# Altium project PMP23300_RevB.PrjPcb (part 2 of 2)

## Sheet PMP23300_PD_Power_RevB.SchDoc
size 431 x 279 mm; Date: Not shown in title block; ApprovedBy: Not shown in title block; CheckedBy: Not shown in title block; Author: Not shown in title block; CompanyName: Not shown in title block; Engineer: Not shown in title block; Organization: Not shown in title block; Address1: Not shown in title block; Address2: Not shown in title block; Address3: Not shown in title block; Address4: Not shown in title block; DocumentNumber: 2; Revision: Use project parameter SCH_Rev; SheetNumber: 2; SheetTotal: 4; PageSetup: Record=PageOptions¦CenterHorizontal=True¦CenterVertical=True¦PrintScale=1.00¦XCorrection=1.00¦YCorrection=1.00¦PrintKind=0¦BorderSize=5000000¦LeftOffset=0¦BottomOffset=0¦Orientation=2¦PaperLength=1000¦PaperWidth=1000¦Scale=100¦PaperSource=15¦PrintQuality=600¦MediaType=1¦DitherType=10¦PaperKind=Letter¦PrintScaleMode=1
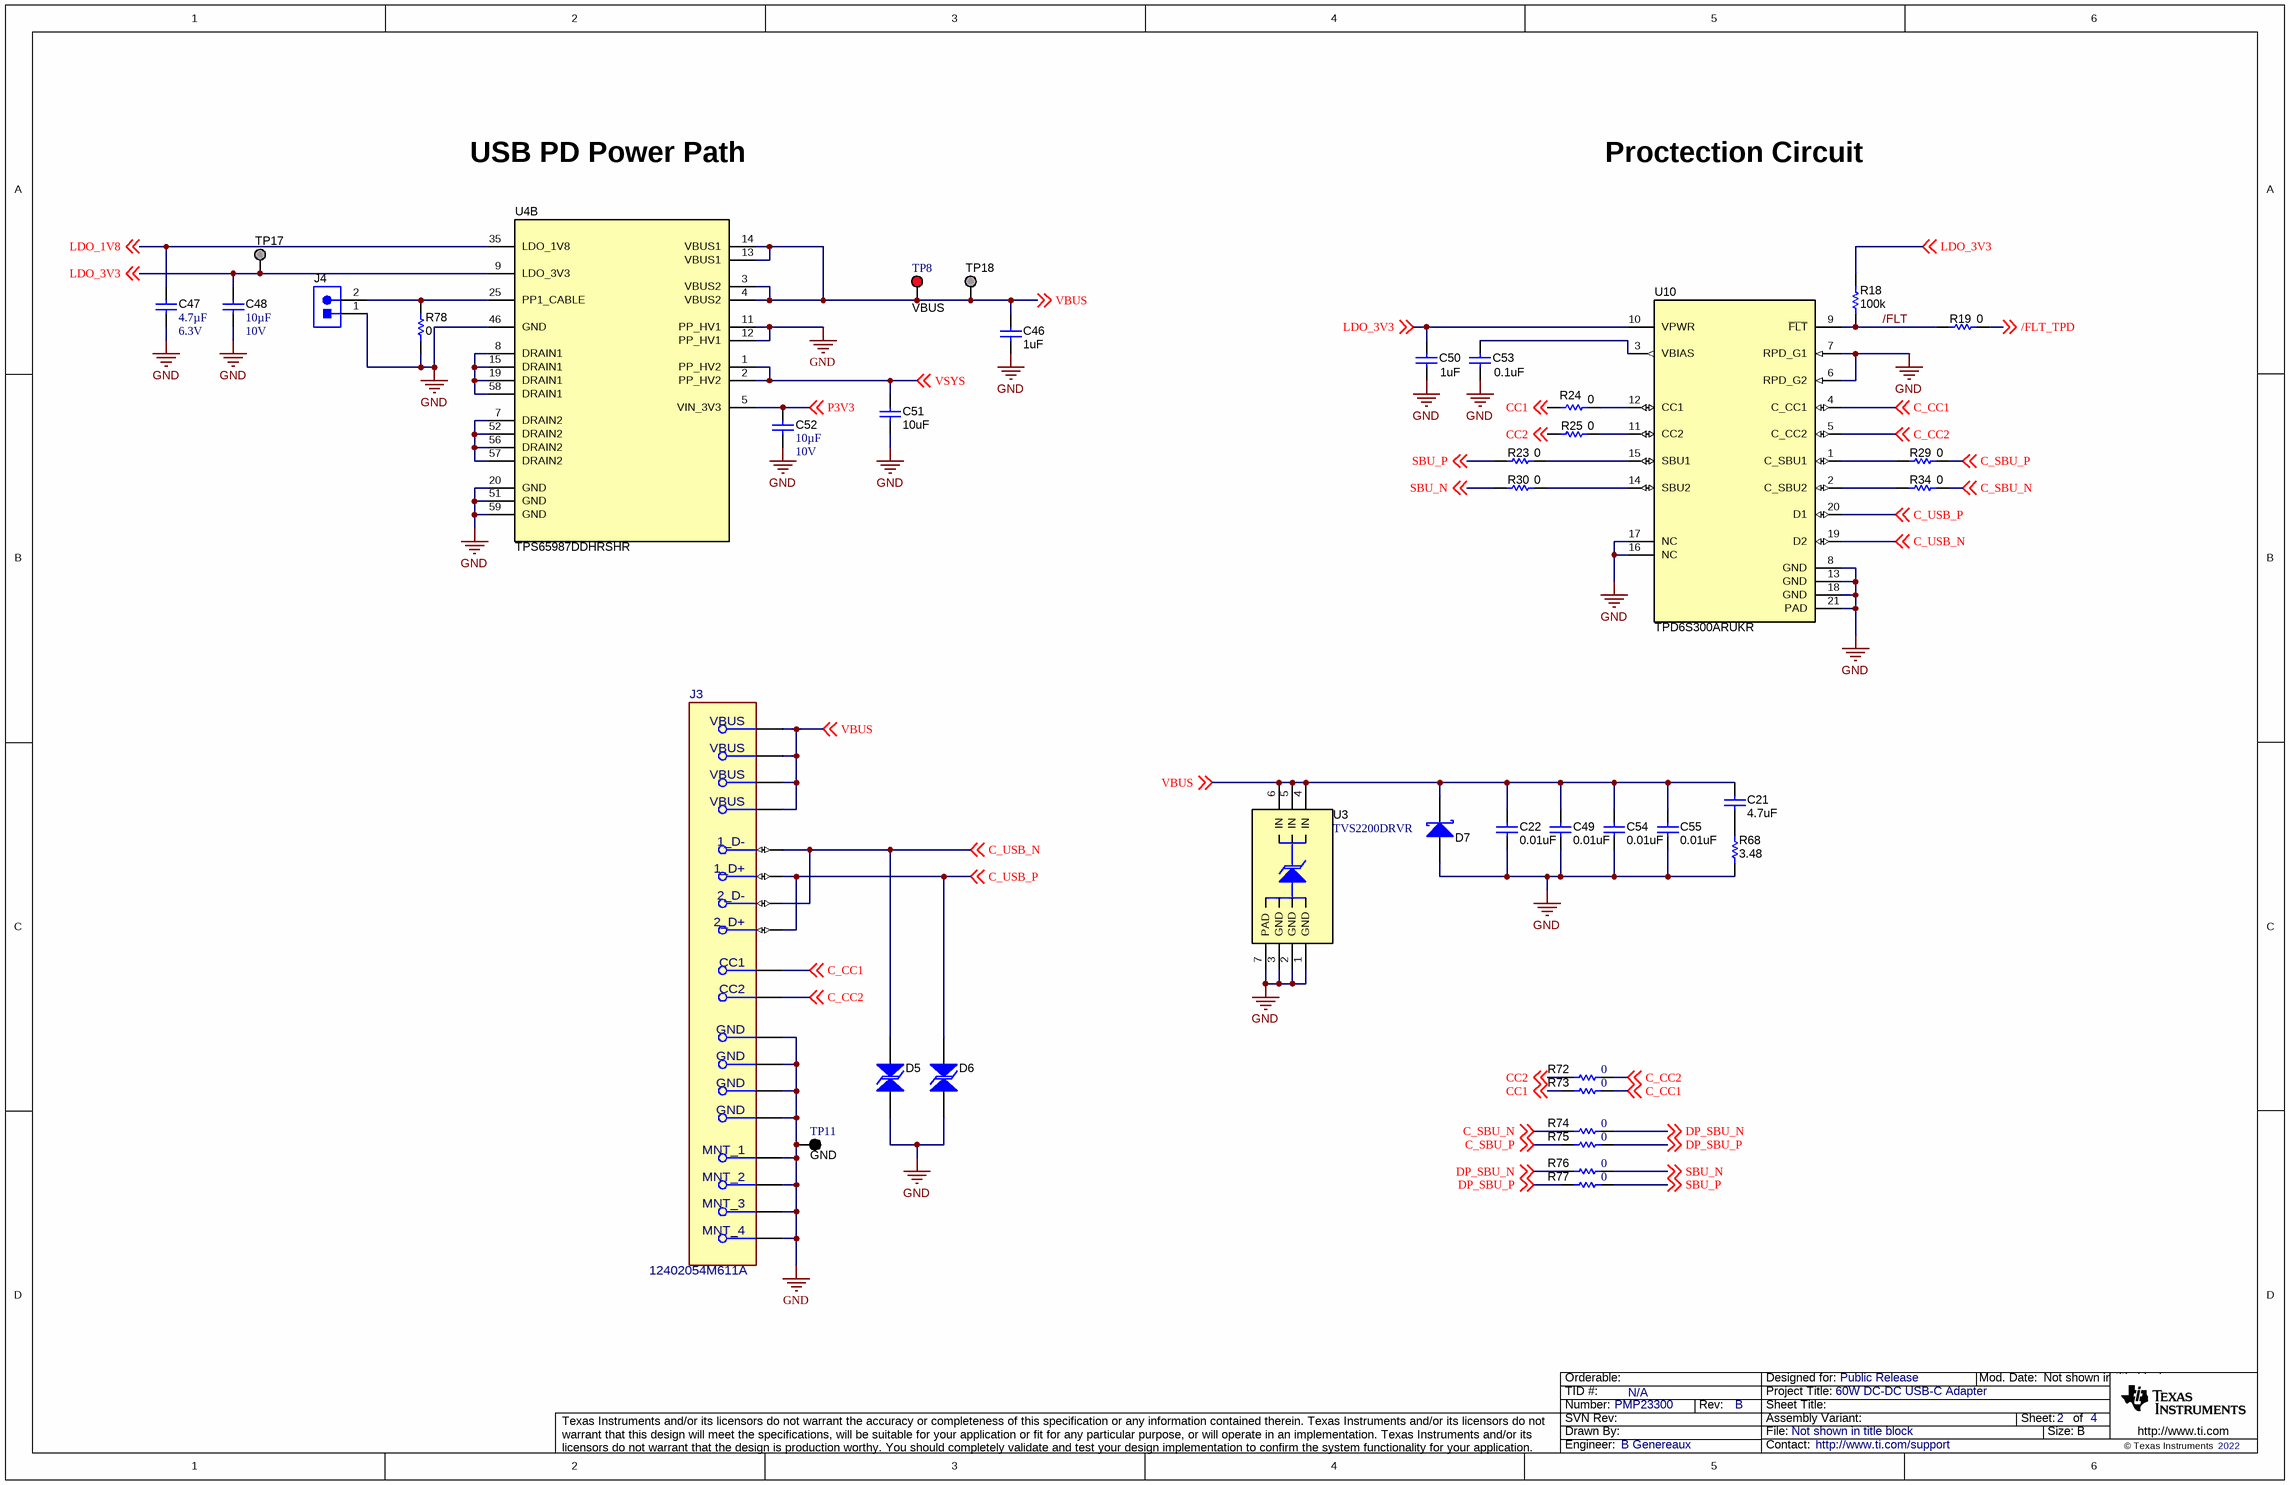
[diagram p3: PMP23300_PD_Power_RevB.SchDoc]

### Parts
C21  ValueDisplayed: 4.7uF  [0603]  (hidden comment: GRM188R6YA475KE15D)
C22  ValueDisplayed: 0.01uF  [0402]  (hidden comment: GCM155R71H103KA55D)
C46  ValueDisplayed: 1uF  [0603]  (hidden comment: UMK107AB7105KA-T)
C47  Cap_F: 4.7µF  VDC_V: 6.3V  [0603]  (hidden comment: JMK107BB7475MA-T)
C48  Cap_F: 10µF  VDC_V: 10V  [0603]  (hidden comment: GRM188Z71A106MA73D)
C49  ValueDisplayed: 0.01uF  [0402]  (hidden comment: GCM155R71H103KA55D)
C50  ValueDisplayed: 1uF  [0402]  (hidden comment: EMK105BJ105KVHF)
C51  ValueDisplayed: 10uF  [0603]  (hidden comment: GRM188R61E106MA73D)
C52  Cap_F: 10µF  VDC_V: 10V  [0603]  (hidden comment: GRM188Z71A106MA73D)
C53  ValueDisplayed: 0.1uF  [0402L]  (hidden comment: GCM155R71H104KE02D)
C54  ValueDisplayed: 0.01uF  [0402]  (hidden comment: GCM155R71H103KA55D)
C55  ValueDisplayed: 0.01uF  [0402]  (hidden comment: GCM155R71H103KA55D)
D5  TPD1E01B04DPLR  [DPL0002A]  (value not drawn)
D6  TPD1E01B04DPLR  [DPL0002A]  (value not drawn)
D7  NSR20F30NXT5G  [DSN2_0603]  (value not drawn)
J3  12402054M611A  [FP-12402054M611A_CONN_USB-MFG]
J4  HTSW-102-09-G-S  [Samtec_HTSW-102-09-x-S]  (value not drawn)
R18  ValueDisplayed: 100k  [0402]  (hidden comment: CRCW0402100KFKED)
R19  ValueDisplayed: 0  [0402]  (hidden comment: RC0402JR-070RL)
R23  ValueDisplayed: 0  [0402]  (hidden comment: RC0402JR-070RL)
R24  ValueDisplayed: 0  [0402]  (hidden comment: RC0402JR-070RL)
R25  ValueDisplayed: 0  [0402]  (hidden comment: RC0402JR-070RL)
R29  ValueDisplayed: 0  [0402]  (hidden comment: RC0402JR-070RL)
R30  ValueDisplayed: 0  [0402]  (hidden comment: RC0402JR-070RL)
R34  ValueDisplayed: 0  [0402]  (hidden comment: RC0402JR-070RL)
R68  ValueDisplayed: 3.48  [0402]  (hidden comment: CRCW04023R48FKED)
R72  ValueDisplayed: 0  [0402]  (hidden comment: RK73Z1ETTP)
R73  ValueDisplayed: 0  [0402]  (hidden comment: RK73Z1ETTP)
R74  ValueDisplayed: 0  [0402]  (hidden comment: RK73Z1ETTP)
R75  ValueDisplayed: 0  [0402]  (hidden comment: RK73Z1ETTP)
R76  ValueDisplayed: 0  [0402]  (hidden comment: RK73Z1ETTP)
R77  ValueDisplayed: 0  [0402]  (hidden comment: RK73Z1ETTP)
R78  ValueDisplayed: 0  [0402]  (hidden comment: RC0402JR-070RL)
TP8  VBUS  [Keystone5010]
TP11  GND  [Keystone5011]
TP17  S1751-46  [Harwin_S1751-46]  (value not drawn)
TP18  S1751-46  [Harwin_S1751-46]  (value not drawn)
U3  TVS2200DRVR  [DRV0006A]
U4  TPS65987DDHRSHR  [RSH0056E]  (part B of 2)
U10  TPD6S300ARUKR  [RUK0020B_NV]

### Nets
GND: C22.2 C46.2 C47.2 C48.2 C49.2 C50.2 C51.2 C52.2 C53.2 C54.2 C55.2 D5.1 D6.1 D7.2(A) J3.1(MNT_1) J3.2(MNT_2) J3.3(MNT_3) J3.4(MNT_4) J3.A1(GND) J3.A12(GND) J3.B1(GND) J3.B12(GND) J4.1 R68.1 R78.1 TP11.1 U3.1(GND) U3.2(GND) U3.3(GND) U3.7(PAD) U4.11(PP_HV1) U4.12(PP_HV1) U4.20(GND) U4.46(GND) U4.51(GND) U4.59(GND) U10.6(RPD_G2) U10.7(RPD_G1) U10.8(GND) U10.13(GND) U10.16(NC) U10.17(NC) U10.18(GND) U10.21(PAD)
/FLT: R18.1 R19.1 U10.9(~{FLT})
/FLT_TPD: R19.2 ; off-sheet /FLT_TPD
C_CC1: J3.A5(CC1) R73.2 U10.4(C_CC1) ; off-sheet C_CC1
C_CC2: J3.B5(CC2) R72.2 U10.5(C_CC2) ; off-sheet C_CC2
C_SBU_N: R34.2 R74.1 ; off-sheet C_SBU_N
C_SBU_P: R29.2 R75.1 ; off-sheet C_SBU_P
C_USB_N: D5.2 J3.A7(1_D-) J3.B7(2_D-) U10.19(D2) ; off-sheet C_USB_N
C_USB_P: D6.2 J3.A6(1_D+) J3.B6(2_D+) U10.20(D1) ; off-sheet C_USB_P
CC1: R24.1 R73.1 ; off-sheet CC1
CC2: R25.1 R72.1 ; off-sheet CC2
DP_SBU_N: R74.2 R76.1 ; off-sheet DP_SBU_N
DP_SBU_P: R75.2 R77.1 ; off-sheet DP_SBU_P
LDO_1V8: C47.1 U4.35(LDO_1V8) ; off-sheet LDO_1V8
LDO_3V3: C48.1 C50.1 R18.2 TP17.1 U4.9(LDO_3V3) U10.10(VPWR) ; off-sheet LDO_3V3
P3V3: C52.1 U4.5(VIN_3V3) ; off-sheet P3V3
SBU_N: R30.1 R76.2 ; off-sheet SBU_N
SBU_P: R23.1 R77.2 ; off-sheet SBU_P
VBUS: C21.2 C22.1 C46.1 C49.1 C54.1 C55.1 D7.1(K) J3.A4(VBUS) J3.A9(VBUS) J3.B4(VBUS) J3.B9(VBUS) TP8.1 TP18.1 U3.4(IN) U3.5(IN) U3.6(IN) U4.3(VBUS2) U4.4(VBUS2) U4.13(VBUS1) U4.14(VBUS1) ; off-sheet VBUS
VSYS: C51.1 U4.1(PP_HV2) U4.2(PP_HV2) ; off-sheet VSYS
NetC21_1: C21.1 R68.2
NetC53_1: C53.1 U10.3(VBIAS)
NetJ4_2: J4.2 R78.2 U4.25(PP1_CABLE)
NetR23_2: R23.2 U10.15(SBU1)
NetR24_2: R24.2 U10.12(CC1)
NetR25_2: R25.2 U10.11(CC2)
NetR29_1: R29.1 U10.1(C_SBU1)
NetR30_2: R30.2 U10.14(SBU2)
NetR34_1: R34.1 U10.2(C_SBU2)
NetU4_7: U4.7(DRAIN2) U4.52(DRAIN2) U4.56(DRAIN2) U4.57(DRAIN2)
NetU4_8: U4.8(DRAIN1) U4.15(DRAIN1) U4.19(DRAIN1) U4.58(DRAIN1)

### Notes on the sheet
- USB PD Power Path
- Proctection Circuit

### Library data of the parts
C21 = CMP-0007357-5: CAP, CERM, 4.7 uF, 35 V, +/- 10%, X5R, 0603; Manufacturer: MuRata; Polarized: N; Value: 4.7uF; U/M: EA; Cap_F: 4.7µF; Value1: Unknown; VDC_V: 35V; TaMin_C: -55°C; TaMax_C: 85°C; SizeArea_mm2: 1.28; SizeAreaWB_mm2: 4.68; SizeX_mm: 1.6; SizeY_mm: 0.8; SizeZ_mm: 1; AEC Category: Q200
C22 C49 C54 C55 = CMP-0006355-2: CAP, CERM, 0.01 uF, 50 V, +/- 10%, C0G/NP0, 0402; Manufacturer: MuRata; Polarized: N; Value: 0.01uF; U/M: EA; Cap_F: 10nF; Value1: Unknown; VDC_V: 50V; TaMin_C: -55°C; TaMax_C: 125°C; AEC Category: Q200; SizeArea_mm2: 0.5; SizeAreaWB_mm2: 3; SizeX_mm: 1; SizeZ_mm: 0.6
C46 = CMP-0007508-5: CAP, CERM, 1 uF, 50 V, +/- 10%, X7R, 0603; Manufacturer: Taiyo Yuden; Polarized: N; Value: 1uF; U/M: EA; Cap_F: 1µF; Value1: Unknown; VDC_V: 50V; TaMin_C: -55°C; TaMax_C: 125°C; SizeArea_mm2: 1.28; SizeAreaWB_mm2: 4.68; SizeX_mm: 1.6; SizeY_mm: 0.8; SizeZ_mm: 1; AEC Category: Q200
C47 = CMP-0007503-4: CAP, CERM, 4.7 uF, 6.3 V, +/- 10%, X7R, 0603; Manufacturer: Taiyo Yuden; TaMin_C: -55°C; Polarized: N; SizeAreaWB_mm2: 4.68; Value1: Unknown; U/M: EA; Value: 4.7uF; TaMax_C: 125°C; SizeZ_mm: 1; SizeX_mm: 1.6; SizeY_mm: 0.8; SizeArea_mm2: 1.28; AEC Category: Q200
C48 C52 = CMP-0007497-5: CAP, CERM, 10 uF, 10 V, +/- 20%, X7R, 0603; Manufacturer: MuRata; TaMin_C: -55°C; Polarized: N; SizeAreaWB_mm2: 4.68; Value1: Unknown; U/M: EA; Value: 10uF; TaMax_C: 125°C; SizeZ_mm: 1; SizeX_mm: 1.6; SizeY_mm: 0.8; SizeArea_mm2: 1.28; AEC Category: Q200
C50 = CMP-0006347-2: CAP, CERM, 1 uF, 16 V, +/- 10%, X5R, 0402; Manufacturer: Taiyo Yuden; TaMin_C: -55°C; Polarized: N; SizeAreaWB_mm2: 3; Value1: Unknown; U/M: EA; Value: 1uF; TaMax_C: 85°C; SizeZ_mm: 0.6; SizeX_mm: 1; SizeY_mm: 0.5; Value2: 16V; Cap_F: 1µF; AEC Category: Q200
C51 = CMP-0007344-5: CAP, CERM, 10 uF, 25 V, +/- 20%, X5R, 0603; Manufacturer: MuRata; Polarized: N; Value: 10uF; U/M: EA; Cap_F: 10µF; Value1: Unknown; VDC_V: 25V; TaMin_C: -55°C; TaMax_C: 85°C; SizeArea_mm2: 1.28; SizeAreaWB_mm2: 4.68; SizeX_mm: 1.6; SizeY_mm: 0.8; SizeZ_mm: 1; AEC Category: Q200
C53 = CMP-0006356-2: CAP, CERM, 0.1 uF, 50 V, +/- 10%, X7R, AEC-Q200 Grade 1, 0402; Manufacturer: MuRata; TaMin_C: -55°C; Polarized: N; SizeAreaWB_mm2: 3; Value1: Unknown; U/M: EA; Value: 0.1uF; TaMax_C: 125°C; SizeZ_mm: 0.6; SizeX_mm: 1; SizeY_mm: 0.5; Cap_Case: 0402; Value2: 50V; AEC Qualified: Y; Cap_F: 100nF; AEC Category: Q200
D5 D6 = CMP-0073601-1: 1-Channel ESD Protection Diode for USB Type-C and Thunderbolt 3, DPL0002A (X2SON-2); Alternate PartNumber: TPD1E01B04DPLT; Alternate Manufacturer: Texas Instruments; SizeAreaWB_mm2: 2.08; U/M: EA; SizeZ_mm: 0.32; SizeX_mm: 0.6; SizeY_mm: 0.3; SizeArea_mm2: 0.18; CompType: IC
D7 = CMP-0028829-1: Diode, Schottky, 30 V, 2 A, 2-XFDFN; Manufacturer: ON Semiconductor; U/M: EA; Vf_V: 4.8dV; Value: 30V; Value1: 2A; Value2: 0.48V; TJmax_C: 150°C; SizeAreaWB_mm2: 4.68; SizeArea_mm2: 1.28; SizeX_mm: 1.6; SizeY_mm: 0.8; SizeZ_mm: 0.31; AEC Category: Q101; AEC Qualified: N; Green_Lifecycle: Not Set; Green_REACh: Incomplete
J3 = CMP-0096733-1: USB-C (USB TYPE-C) USB 2.0 Receptacle Connector 24 (14+10 Dummy) Position Through Hole, Right Angle; Manufacturer: Amphenol ICC; Current_A: 3A; AEC Qualified: No; SizeZ_mm: 9.24mm; Shrouded: true; Usb Standard: USB 2.0; Is Female: yes; ContactFinish: Gold,Nickel
J4 = CMP-0075626-1: Header, 100mil, 2x1, Gold, TH; Manufacturer: Samtec; Pitch_mm: 2.54; Gender: Male; Cert_CSA: Y; CT: False; Row_Count: 1
R18 = CMP-0025950-3: RES, 100 k, 1%, 0.063 W, AEC-Q200 Grade 0, 0402; Manufacturer: Vishay-Dale; Value: 100k; Power_W: 63mW; Value2: 0.063W; VDC_V: 50V; TempCo: 100 ppm/C; SizeArea_mm2: 0.5; SizeX_mm: 1; SizeZ_mm: 0.6; EIA_Code: E96; AEC Category: Q200; AEC Qualified: Y; AEC Grade: 0
R19 R23-R25 R29 R30 R34 R78 = CMP-0027004-2: RES, 0, 5%, 0.063 W, 0402; Manufacturer: Yageo America; Power_W: 63mW; TempCo: 200 ppm/C; Value_Code: 0000; U/M: EA; Value: 0; EIA_Code: E24; SizeX_mm: 1; SizeY_mm: 0.5; SizeZ_mm: 0.6; Value2: 0.063W; VDC_V: 50V; AEC Category: Q200
R68 = CMP-0026359-2: RES, 3.48, 1%, 0.063 W, AEC-Q200 Grade 0, 0402; Manufacturer: Vishay-Dale; Value: 3.48; Value_Code: 3R48; Power_W: 63mW; Value2: 0.063W; VDC_V: 50V; TempCo: 100 ppm/C; SizeArea_mm2: 0.5; SizeX_mm: 1; SizeZ_mm: 0.6; EIA_Code: E96; AEC Category: Q200; AEC Qualified: Y; AEC Grade: 0
R72-R77 = CMP-0027007-2: RES, 0, 5%, 0.063 W, AEC-Q200 Grade 0, 0402; Manufacturer: KOA Speer; Power_W: 63mW; TempCo: ppm/C; Value_Code: 0000; U/M: EA; Value: 0; EIA_Code: E24; SizeX_mm: 1; SizeY_mm: 0.5; SizeZ_mm: 0.6; Value2: 0.063W; AEC Qualified: Y; AEC Category: Q200
TP8 = CMP-0055147-2: Test Point, Multipurpose, Red, TH; Manufacturer: Keystone Electronics; CT: TRUE; ContactFinish: Silver; Green_Lifecycle: Active; CNHeader: FALSE; Green_REACh: Passed
TP11 = CMP-0055148-2: Test Point, Multipurpose, Black, TH; Manufacturer: Keystone Electronics; CNHeader: FALSE; ContactFinish: Silver; Green_REACh: Passed; Green_Lifecycle: Active; CT: TRUE
TP17 TP18 = CMP-0075188-1: Test Lead clips and hooks, SMT; Manufacturer: Harwin; CNHeader: False; Current_A: 2A; CompType: Test Point; ContactFinish: Tin; CT: True
U3 = CMP-0077834-1: 22-V Precision Surge Protection Clamp, DRV0006A (WSON-6); Alternate Manufacturer: Texas Instruments; SizeAreaWB_mm2: 9.0; SizeZ_mm: 0.8; SizeX_mm: 2.0; SizeArea_mm2: 4.0; CompType: IC; AEC Qualified: N; AEC Category: Q200
U4 = CMP-0081032-2: USB Type-C and USB PD Controller with Integrated Power Switches, RSH0056E (VQFN-56); Alternate PartNumber: TPS65987DDHRSHT; Alternate Manufacturer: Texas Instruments; SizeAreaWB_mm2: 81; SizeZ_mm: 1; SizeX_mm: 7; SizeArea_mm2: 49; CompType: IC; AEC Qualified: N; AEC Category: Q200
U10 = CMP-0081565-1: USB Type-C Port Protector: Short-to-VBUS Overvoltage and IEC ESD Protection, RUK0020B (WQFN-20); Alternate Manufacturer: Texas Instruments; SizeAreaWB_mm2: 16; SizeZ_mm: 0.8; SizeX_mm: 3; SizeArea_mm2: 9; CompType: IC; AEC Qualified: N; AEC Category: Q200

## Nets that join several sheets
GND: PMP23300_DC-DC_RevB (55 pins), PMP23300_PD_Control_RevB (12 pins), PMP23300_TIVA_RevB (37 pins), PMP23300_PD_Power_RevB (44 pins)
/FLT_TPD: PMP23300_PD_Control_RevB (U4.31), PMP23300_PD_Power_RevB (R19.2)
C_USB_N: PMP23300_PD_Control_RevB (R17.2), PMP23300_PD_Power_RevB (D5.2 J3.A7 J3.B7 U10.19)
C_USB_P: PMP23300_PD_Control_RevB (R7.2), PMP23300_PD_Power_RevB (D6.2 J3.A6 J3.B6 U10.20)
CC1: PMP23300_PD_Control_RevB (C23.1 U4.24), PMP23300_PD_Power_RevB (R24.1 R73.1)
CC2: PMP23300_PD_Control_RevB (C24.1 U4.26), PMP23300_PD_Power_RevB (R25.1 R72.1)
I2C1_IRQZ: PMP23300_PD_Control_RevB (R22.2 U4.29), PMP23300_TIVA_RevB (R82.2)
I2C1_SCL: PMP23300_PD_Control_RevB (R20.2 U4.27), PMP23300_TIVA_RevB (R83.2)
I2C1_SDA: PMP23300_PD_Control_RevB (R21.2 U4.28), PMP23300_TIVA_RevB (R84.2)
I2C2_IRQZ: PMP23300_PD_Control_RevB (R26.2 U4.34), PMP23300_TIVA_RevB (R48.2)
I2C2_SCL: PMP23300_PD_Control_RevB (R28.2 U4.32), PMP23300_TIVA_RevB (R49.2 R51.2)
I2C2_SDA: PMP23300_PD_Control_RevB (R27.2 U4.33), PMP23300_TIVA_RevB (R50.2 R53.2)
LDO_3V3: PMP23300_PD_Control_RevB (14 pins), PMP23300_PD_Power_RevB (6 pins)
P3V3: PMP23300_DC-DC_RevB (12 pins), PMP23300_PD_Control_RevB (R31.2), PMP23300_PD_Power_RevB (C52.1 U4.5)
PDO_0: PMP23300_DC-DC_RevB (Q4.1 TP19.1), PMP23300_PD_Control_RevB (U4.42)
PDO_1: PMP23300_DC-DC_RevB (Q1.1 Q5.1 R11.2 TP20.1), PMP23300_PD_Control_RevB (U4.43)
PDO_2: PMP23300_DC-DC_RevB (Q2.1 Q6.1 R12.2 TP21.1), PMP23300_PD_Control_RevB (U4.49)
PDO_3: PMP23300_DC-DC_RevB (Q3.1 Q7.1 R13.2 TP22.1), PMP23300_PD_Control_RevB (U4.54)
SPI_CLK: PMP23300_PD_Control_RevB (U4.38 U5.6), PMP23300_TIVA_RevB (R52.2 R66.2)
SPI_CSZ: PMP23300_PD_Control_RevB (R39.2 U4.39 U5.1), PMP23300_TIVA_RevB (R47.2 R80.2)
SPI_MISO: PMP23300_PD_Control_RevB (5 pins), PMP23300_TIVA_RevB (R54.2 R65.2)
SPI_MOSI: PMP23300_PD_Control_RevB (U4.37 U5.5), PMP23300_TIVA_RevB (R62.1 R67.2)
VSYS: PMP23300_DC-DC_RevB (9 pins), PMP23300_PD_Power_RevB (C51.1 U4.1 U4.2)

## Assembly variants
001: not fitted C7 R8 R33 R44 R53 R54 R72 R73 R74 R75 R76 R77 TP5 TP9 TP10 TP12 TP13 TP14 TP15 TP16 TP17 TP18 TP19 TP20 TP21 TP22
